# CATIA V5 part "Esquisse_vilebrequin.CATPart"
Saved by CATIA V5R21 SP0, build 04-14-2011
Part number: Part1
Bounding box of the stored display mesh (mm): x 0 to 46, y 0 to 6.25, z 0 to 0
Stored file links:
  C:\Users\Olivier\Desktop\redaction CATIA (local)\CATIA\DONNEES\Exercice esquisse 2 (vilebrequin)\Esquisse_vilebrequin.CATPart
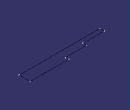
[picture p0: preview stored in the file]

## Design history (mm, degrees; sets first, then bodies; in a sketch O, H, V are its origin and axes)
AxisSystem1: origin (0, 0, 0), X (1, 0, 0), Y (0, 1, 0), Z (0, 0, 1)
Body1 (main body)
  Sketch1 on xy-plane, origin (0, 0, 0), H (1, 0, 0), V (0, 1, 0)
    point P1 (0, 0)
    line L1 (0, 0) -> (46, 0)
    line L2 (46, 0) -> (46, 6.25)
    line L3 (46, 6.25) -> (24, 6.25)
    line L4 (24, 6.25) -> (24, 4.5)
    line L5 (24, 4.5) -> (12, 4.5)
    line L6 (12, 4.5) -> (12, 2.5)
    line L7 (12, 2.5) -> (0, 2.5)
    line L8 (0, 2.5) -> (0, 0)
    distance L8 L2 = 46
    length L8 = 2.5
    length L7 = 12
    distance L4 L8 = 24
    distance L3 L1 = 6.25
    distance L5 L1 = 4.5
    horizontal: L1 H, L3 H, L5 H, L7 H
    vertical: L2 V, L4 V, L6 V, L8 V
    coincidence: P1 O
